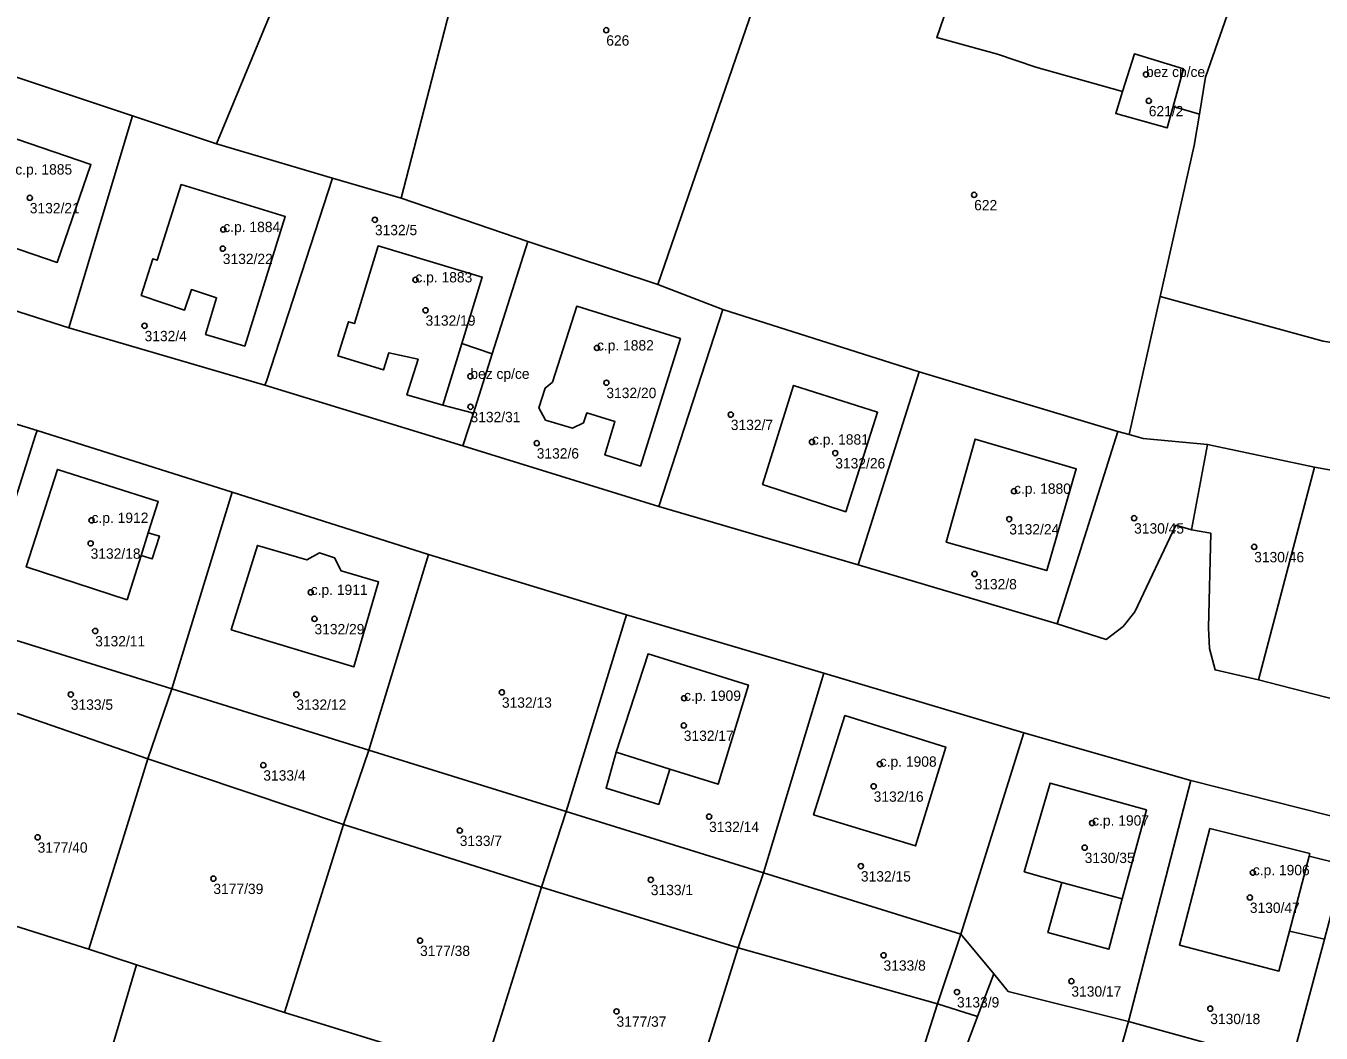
# Model space of a CAD drawing. Extents: x -878211 to -870363, y -1058464 to -1052522.
# Drawn here: x -874523.6 to -874398.3, y -1056692 to -1056594.5 of the extents above; entities that cross this region are included whole.
import ezdxf

# ---------------------------------------------------------------- set-up
doc = ezdxf.new("R2010")
doc.units = 0
for name, color, linetype in [('Definiční body', 7, 'Continuous'), ('Polygon budovy', 7, 'Continuous'), ('Polygon parcely', 7, 'Continuous')]:
    doc.layers.add(name, color=color, linetype=linetype)

msp = doc.modelspace()

# ---------------------------------------------------------------- linework, layer by layer
at = {"layer": 'Definiční body'}
for centre in [(-874467.44, -1056594.87994), (-874415.21, -1056599.15994), (-874414.94, -1056601.71994), (-874523.23, -1056611.10994), (-874431.84, -1056610.81994), (-874504.5, -1056614.16994), (-874489.83, -1056613.22994), (-874504.55, -1056616.01994), (-874485.91, -1056619.03994), (-874484.93, -1056621.98994), (-874512.12, -1056623.48994), (-874468.34, -1056625.62994), (-874480.59, -1056628.37994), (-874467.43, -1056628.99994), (-874480.58, -1056631.32994), (-874455.39, -1056632.08994), (-874474.17, -1056634.84994), (-874447.53, -1056634.73994), (-874445.28, -1056635.80994), (-874427.98, -1056639.49994), (-874517.25, -1056642.31994), (-874428.44, -1056642.19994), (-874416.36, -1056642.10994), (-874517.34, -1056644.54994), (-874404.74, -1056644.88994), (-874431.8, -1056647.50994), (-874496.04, -1056649.28994), (-874495.68, -1056651.85994), (-874516.9, -1056653.02994), (-874519.26, -1056659.16994), (-874497.43, -1056659.16994), (-874477.54, -1056658.96994), (-874459.91, -1056659.53994), (-874459.94, -1056662.17994), (-874500.63, -1056666.01994), (-874440.97, -1056665.91994), (-874441.56, -1056668.06994), (-874457.49, -1056670.99994), (-874420.42, -1056671.61994), (-874522.47, -1056672.99994), (-874481.62, -1056672.34994), (-874421.14, -1056673.99994), (-874505.46, -1056676.99994), (-874442.8, -1056675.78994), (-874404.87, -1056676.41994), (-874463.13, -1056677.10994), (-874405.16, -1056678.82994), (-874485.46, -1056682.99994), (-874440.61, -1056684.41994), (-874422.43, -1056686.92994), (-874433.5, -1056687.97994), (-874466.45, -1056689.84994), (-874408.99, -1056689.58994)]:
    msp.add_circle(centre, 0.25, dxfattribs=at)
at = {"layer": 'Polygon budovy'}
for points in [[(-874417.47, -1056600.82), (-874418.14, -1056602.93), (-874413.16, -1056604.33), (-874412.58, -1056602.26), (-874411.58, -1056598.63), (-874416.33, -1056597.18)], [(-874530.12, -1056614.09), (-874520.57, -1056617.36), (-874517.32, -1056607.88), (-874526.88, -1056604.61)], [(-874508.25, -1056621.96), (-874507.58, -1056619.98), (-874505.15, -1056620.78), (-874506.21, -1056624.33), (-874502.43, -1056625.46), (-874498.5, -1056612.91), (-874508.59, -1056609.82), (-874510.89, -1056617.14), (-874511.33, -1056617), (-874512.45, -1056620.54)], [(-874493.41, -1056626.4), (-874489, -1056627.76), (-874488.48, -1056626.09), (-874485.66, -1056626.72), (-874486.73, -1056630.16), (-874483.25, -1056631.18), (-874481.42, -1056625.19), (-874479.46, -1056618.78), (-874489.51, -1056615.75), (-874491.82, -1056623.27), (-874492.38, -1056623.09)], [(-874473.36, -1056629.52), (-874473.96, -1056631.43), (-874473.32, -1056632.62), (-874470.71, -1056633.4), (-874469.63, -1056632.87), (-874469.33, -1056631.92), (-874466.6, -1056632.74), (-874467.58, -1056635.97), (-874464.13, -1056637.06), (-874460.26, -1056624.73), (-874470.3, -1056621.59), (-874472.65, -1056628.94)], [(-874480.3, -1056631.93), (-874478.49, -1056626.21), (-874481.42, -1056625.19), (-874483.25, -1056631.18)], [(-874452.32, -1056638.84), (-874444.26, -1056641.48), (-874441.18, -1056631.86), (-874449.31, -1056629.26)], [(-874434.54, -1056644.43), (-874424.82, -1056647.18), (-874421.96, -1056637.32), (-874431.73, -1056634.46)], [(-874512.46, -1056645.71), (-874511.76, -1056643.53), (-874510.8, -1056640.5), (-874520.55, -1056637.39), (-874523.57, -1056646.83), (-874513.82, -1056650)], [(-874503.74, -1056652.91), (-874491.88, -1056656.51), (-874489.47, -1056648.28), (-874493.08, -1056647.22), (-874493.73, -1056645.94), (-874495.18, -1056645.48), (-874496.42, -1056646.15), (-874501.2, -1056644.75)], [(-874466.47, -1056664.75), (-874461.3, -1056666.41), (-874456.6, -1056667.86), (-874453.68, -1056658.26), (-874463.4, -1056655.24)], [(-874447.38, -1056670.81), (-874437.51, -1056673.84), (-874434.59, -1056664.26), (-874444.34, -1056661.21)], [(-874426.99, -1056676.34), (-874423.34, -1056677.37), (-874417.51, -1056678.97), (-874415.17, -1056670.35), (-874424.49, -1056667.76)], [(-874399.37, -1056674.57), (-874409.02, -1056672.15), (-874411.97, -1056683.44), (-874402.34, -1056685.95), (-874401.33, -1056682.07), (-874399.42, -1056674.81)]]:
    msp.add_lwpolyline(points, close=True, dxfattribs=at)
at = {"layer": 'Polygon parcely'}
for points in [[(-874482.68, -1056552), (-874492.23, -1056574.63), (-874505.17, -1056605.89), (-874493.95, -1056609.2), (-874487.28, -1056611.12), (-874472.96, -1056555.68), (-874476.32, -1056554.41), (-874477.4, -1056553.99)], [(-874472.96, -1056555.68), (-874487.28, -1056611.12), (-874475.03, -1056615.34), (-874462.44, -1056619.5), (-874452.28, -1056589.96), (-874459.59, -1056587.43), (-874457.06, -1056577.35), (-874452.98, -1056562.31), (-874459.26, -1056559.96), (-874463.6, -1056558.33), (-874472.65, -1056554.94)], [(-874492.23, -1056574.63), (-874501.67, -1056571.24), (-874510.67, -1056567.24), (-874515.54, -1056565.34), (-874527.34, -1056598.5), (-874513.29, -1056603.18), (-874505.17, -1056605.89)], [(-874399.15, -1056580.65), (-874413.96, -1056575.21), (-874417.44, -1056579.26), (-874424.45, -1056585.79), (-874431.52, -1056583.55), (-874433.84, -1056591.24), (-874434.41, -1056592.58), (-874435.46, -1056595.57), (-874429.59, -1056597.21), (-874425.86, -1056598.45), (-874417.47, -1056600.82), (-874416.33, -1056597.18), (-874411.58, -1056598.63), (-874412.58, -1056602.26), (-874410.04, -1056603), (-874409.44, -1056599.43), (-874406.65, -1056591.37)], [(-874425.86, -1056598.45), (-874429.59, -1056597.21), (-874435.46, -1056595.57), (-874434.41, -1056592.58), (-874433.84, -1056591.24), (-874431.52, -1056583.55), (-874448.75, -1056579.37), (-874457.06, -1056577.35), (-874459.59, -1056587.43), (-874452.28, -1056589.96), (-874462.44, -1056619.5), (-874456.17, -1056621.91), (-874437.15, -1056627.95), (-874417.92, -1056633.73), (-874416.85, -1056634), (-874413.84, -1056620.64), (-874410.55, -1056606.05), (-874410.04, -1056603), (-874412.58, -1056602.26), (-874413.16, -1056604.33), (-874418.14, -1056602.93), (-874417.47, -1056600.82)], [(-874390.92, -1056582.93), (-874399.15, -1056580.65), (-874406.65, -1056591.37), (-874409.44, -1056599.43), (-874410.04, -1056603), (-874410.55, -1056606.05), (-874413.84, -1056620.64), (-874398.08, -1056624.97), (-874371.71, -1056629.09), (-874371.71, -1056611.62), (-874372.19, -1056611.57), (-874375.58, -1056611.24), (-874381.94, -1056609.81), (-874392.72, -1056607.44), (-874392.18, -1056604.62), (-874390.79, -1056601.51)], [(-874519.44, -1056623.7), (-874513.29, -1056603.18), (-874527.34, -1056598.5), (-874531.91, -1056597.08), (-874538.75, -1056617.53)], [(-874413.16, -1056604.33), (-874412.58, -1056602.26), (-874411.58, -1056598.63), (-874416.33, -1056597.18), (-874417.47, -1056600.82), (-874418.14, -1056602.93)], [(-874500.32, -1056628.85), (-874493.95, -1056609.2), (-874505.17, -1056605.89), (-874513.29, -1056603.18), (-874519.44, -1056623.7), (-874500.47, -1056629.25)], [(-874526.88, -1056604.61), (-874530.12, -1056614.09), (-874520.57, -1056617.36), (-874517.32, -1056607.88)], [(-874526.88, -1056604.61), (-874517.32, -1056607.88), (-874520.57, -1056617.36), (-874530.12, -1056614.09)], [(-874510.89, -1056617.14), (-874511.33, -1056617), (-874512.45, -1056620.54), (-874508.25, -1056621.96), (-874507.58, -1056619.98), (-874505.15, -1056620.78), (-874506.21, -1056624.33), (-874502.43, -1056625.46), (-874498.5, -1056612.91), (-874508.59, -1056609.82)], [(-874510.89, -1056617.14), (-874508.59, -1056609.82), (-874498.5, -1056612.91), (-874502.43, -1056625.46), (-874506.21, -1056624.33), (-874505.15, -1056620.78), (-874507.58, -1056619.98), (-874508.25, -1056621.96), (-874512.45, -1056620.54), (-874511.33, -1056617)], [(-874489.51, -1056615.75), (-874479.46, -1056618.78), (-874481.42, -1056625.19), (-874478.49, -1056626.21), (-874475.03, -1056615.34), (-874487.28, -1056611.12), (-874493.95, -1056609.2), (-874500.32, -1056628.85), (-874500.47, -1056629.25), (-874481.31, -1056635.12), (-874480.3, -1056631.93), (-874483.25, -1056631.18), (-874486.73, -1056630.16), (-874485.66, -1056626.72), (-874488.48, -1056626.09), (-874489, -1056627.76), (-874493.41, -1056626.4), (-874492.38, -1056623.09), (-874491.82, -1056623.27)], [(-874456.17, -1056621.91), (-874462.44, -1056619.5), (-874475.03, -1056615.34), (-874478.49, -1056626.21), (-874480.3, -1056631.93), (-874481.31, -1056635.12), (-874462.35, -1056640.98)], [(-874483.25, -1056631.18), (-874481.42, -1056625.19), (-874479.46, -1056618.78), (-874489.51, -1056615.75), (-874491.82, -1056623.27), (-874492.38, -1056623.09), (-874493.41, -1056626.4), (-874489, -1056627.76), (-874488.48, -1056626.09), (-874485.66, -1056626.72), (-874486.73, -1056630.16)], [(-874464.13, -1056637.06), (-874467.58, -1056635.97), (-874466.6, -1056632.74), (-874469.33, -1056631.92), (-874469.63, -1056632.87), (-874470.71, -1056633.4), (-874473.32, -1056632.62), (-874473.96, -1056631.43), (-874473.36, -1056629.52), (-874472.65, -1056628.94), (-874470.3, -1056621.59), (-874460.26, -1056624.73)], [(-874464.13, -1056637.06), (-874460.26, -1056624.73), (-874470.3, -1056621.59), (-874472.65, -1056628.94), (-874473.36, -1056629.52), (-874473.96, -1056631.43), (-874473.32, -1056632.62), (-874470.71, -1056633.4), (-874469.63, -1056632.87), (-874469.33, -1056631.92), (-874466.6, -1056632.74), (-874467.58, -1056635.97)], [(-874415.48, -1056634.41), (-874409.26, -1056634.97), (-874398.9, -1056637.18), (-874380.41, -1056640.49), (-874372.85, -1056641.69), (-874371.71, -1056629.09), (-874398.08, -1056624.97), (-874413.84, -1056620.64), (-874416.85, -1056634)], [(-874437.15, -1056627.95), (-874456.17, -1056621.91), (-874462.35, -1056640.98), (-874443.06, -1056646.64)], [(-874478.49, -1056626.21), (-874481.42, -1056625.19), (-874483.25, -1056631.18), (-874480.3, -1056631.93)], [(-874547.67, -1056646.74), (-874528.58, -1056652.68), (-874522.69, -1056634.07), (-874522.52, -1056633.61), (-874542.01, -1056627.68)], [(-874417.92, -1056633.73), (-874437.15, -1056627.95), (-874443.06, -1056646.64), (-874423.82, -1056652.34)], [(-874449.31, -1056629.26), (-874441.18, -1056631.86), (-874444.26, -1056641.48), (-874452.32, -1056638.84)], [(-874449.31, -1056629.26), (-874452.32, -1056638.84), (-874444.26, -1056641.48), (-874441.18, -1056631.86)], [(-874509.49, -1056658.62), (-874503.66, -1056639.59), (-874522.52, -1056633.61), (-874522.69, -1056634.07), (-874528.58, -1056652.68)], [(-874410.8, -1056643.23), (-874409.26, -1056634.97), (-874415.48, -1056634.41), (-874416.85, -1056634), (-874417.92, -1056633.73), (-874423.82, -1056652.34), (-874419.07, -1056653.84), (-874417.43, -1056652.61), (-874416.29, -1056651.16), (-874412.32, -1056642.79)], [(-874421.96, -1056637.32), (-874424.82, -1056647.18), (-874434.54, -1056644.43), (-874431.73, -1056634.46)], [(-874421.96, -1056637.32), (-874431.73, -1056634.46), (-874434.54, -1056644.43), (-874424.82, -1056647.18)], [(-874410.8, -1056643.23), (-874408.93, -1056643.57), (-874409.16, -1056652.73), (-874409.07, -1056654.73), (-874408.53, -1056656.8), (-874404.31, -1056657.76), (-874398.9, -1056637.18), (-874409.26, -1056634.97)], [(-874523.57, -1056646.83), (-874520.55, -1056637.39), (-874510.8, -1056640.5), (-874511.76, -1056643.53), (-874510.69, -1056643.85), (-874511.38, -1056646.05), (-874512.46, -1056645.71), (-874513.82, -1056650)], [(-874523.57, -1056646.83), (-874513.82, -1056650), (-874512.46, -1056645.71), (-874511.38, -1056646.05), (-874510.69, -1056643.85), (-874511.76, -1056643.53), (-874510.8, -1056640.5), (-874520.55, -1056637.39)], [(-874380.41, -1056640.49), (-874398.9, -1056637.18), (-874404.31, -1056657.76), (-874385.91, -1056662.51)], [(-874490.41, -1056664.56), (-874484.66, -1056645.64), (-874503.66, -1056639.59), (-874509.49, -1056658.62)], [(-874493.73, -1056645.94), (-874493.08, -1056647.22), (-874489.47, -1056648.28), (-874491.88, -1056656.51), (-874503.74, -1056652.91), (-874501.2, -1056644.75), (-874496.42, -1056646.15), (-874495.18, -1056645.48)], [(-874493.73, -1056645.94), (-874495.18, -1056645.48), (-874496.42, -1056646.15), (-874501.2, -1056644.75), (-874503.74, -1056652.91), (-874491.88, -1056656.51), (-874489.47, -1056648.28), (-874493.08, -1056647.22)], [(-874465.47, -1056651.46), (-874484.66, -1056645.64), (-874490.41, -1056664.56), (-874471.32, -1056670.5)], [(-874446.38, -1056657.11), (-874465.47, -1056651.46), (-874471.32, -1056670.5), (-874452.23, -1056676.43)], [(-874528.58, -1056652.68), (-874530.51, -1056658.93), (-874511.82, -1056665.4), (-874509.49, -1056658.62)], [(-874453.68, -1056658.26), (-874463.4, -1056655.24), (-874466.47, -1056664.75), (-874467.46, -1056668.23), (-874462.36, -1056669.82), (-874461.3, -1056666.41), (-874456.6, -1056667.86)], [(-874453.68, -1056658.26), (-874456.6, -1056667.86), (-874461.3, -1056666.41), (-874462.36, -1056669.82), (-874467.46, -1056668.23), (-874466.47, -1056664.75), (-874463.4, -1056655.24)], [(-874427.04, -1056662.88), (-874446.38, -1056657.11), (-874452.23, -1056676.43), (-874433.14, -1056682.38)], [(-874536.59, -1056677.84), (-874517.53, -1056683.84), (-874511.82, -1056665.4), (-874530.51, -1056658.93)], [(-874509.49, -1056658.62), (-874511.82, -1056665.4), (-874492.86, -1056671.77), (-874490.41, -1056664.56)], [(-874437.51, -1056673.84), (-874434.59, -1056664.26), (-874444.34, -1056661.21), (-874447.38, -1056670.81)], [(-874437.51, -1056673.84), (-874447.38, -1056670.81), (-874444.34, -1056661.21), (-874434.59, -1056664.26)], [(-874427.04, -1056662.88), (-874433.14, -1056682.38), (-874429.95, -1056686.22), (-874428.55, -1056687.91), (-874416.89, -1056690.83), (-874410.86, -1056667.5)], [(-874512.89, -1056685.34), (-874498.58, -1056689.97), (-874492.86, -1056671.77), (-874511.82, -1056665.4), (-874517.53, -1056683.84)], [(-874473.72, -1056677.82), (-874471.32, -1056670.5), (-874490.41, -1056664.56), (-874492.86, -1056671.77)], [(-874417.51, -1056678.97), (-874418.8, -1056683.83), (-874424.7, -1056682.21), (-874423.34, -1056677.37), (-874426.99, -1056676.34), (-874424.49, -1056667.76), (-874415.17, -1056670.35)], [(-874417.51, -1056678.97), (-874415.17, -1056670.35), (-874424.49, -1056667.76), (-874426.99, -1056676.34), (-874423.34, -1056677.37), (-874424.7, -1056682.21), (-874418.8, -1056683.83)], [(-874409.02, -1056672.15), (-874399.37, -1056674.57), (-874399.42, -1056674.81), (-874396.04, -1056675.67), (-874394.94, -1056671.52), (-874410.86, -1056667.5), (-874416.89, -1056690.83), (-874401.22, -1056695.15), (-874397.95, -1056682.85), (-874401.33, -1056682.07), (-874402.34, -1056685.95), (-874411.97, -1056683.44)], [(-874471.32, -1056670.5), (-874473.72, -1056677.82), (-874454.69, -1056683.71), (-874452.23, -1056676.43)], [(-874396.04, -1056675.67), (-874397.95, -1056682.85), (-874401.22, -1056695.15), (-874385.04, -1056699.32), (-874378.88, -1056675.53), (-874394.94, -1056671.52)], [(-874479.36, -1056695.89), (-874473.72, -1056677.82), (-874492.86, -1056671.77), (-874498.58, -1056689.97)], [(-874396.04, -1056675.67), (-874399.42, -1056674.81), (-874399.37, -1056674.57), (-874409.02, -1056672.15), (-874411.97, -1056683.44), (-874402.34, -1056685.95), (-874401.33, -1056682.07), (-874397.95, -1056682.85)], [(-874520.36, -1056710.57), (-874519.51, -1056707.69), (-874514.47, -1056705.1), (-874517.18, -1056699.85), (-874512.89, -1056685.34), (-874517.53, -1056683.84), (-874536.59, -1056677.84), (-874541.03, -1056676.46), (-874548.64, -1056702.2)], [(-874433.14, -1056682.38), (-874452.23, -1056676.43), (-874454.69, -1056683.71), (-874435.39, -1056689.11)], [(-874473.72, -1056677.82), (-874479.36, -1056695.89), (-874460.36, -1056701.86), (-874454.69, -1056683.71)], [(-874435.39, -1056689.11), (-874431.5, -1056690.35), (-874429.95, -1056686.22), (-874433.14, -1056682.38)], [(-874454.69, -1056683.71), (-874460.36, -1056701.86), (-874441.33, -1056707.79), (-874438.87, -1056700.06), (-874435.39, -1056689.11)], [(-874512.89, -1056685.34), (-874517.18, -1056699.85), (-874514.47, -1056705.1), (-874511.88, -1056710.13), (-874494.62, -1056715.24), (-874486.23, -1056717.71), (-874482.63, -1056706.27), (-874479.36, -1056695.89), (-874498.58, -1056689.97)], [(-874429.95, -1056686.22), (-874431.5, -1056690.35), (-874435.46, -1056700.9), (-874420.78, -1056704.5), (-874416.89, -1056690.83), (-874428.55, -1056687.91)], [(-874438.87, -1056700.06), (-874441.33, -1056707.79), (-874438.03, -1056708.82), (-874435.46, -1056700.9), (-874431.5, -1056690.35), (-874435.39, -1056689.11)], [(-874404.63, -1056708.63), (-874401.71, -1056697.09), (-874401.22, -1056695.15), (-874416.89, -1056690.83), (-874420.78, -1056704.5)]]:
    msp.add_lwpolyline(points, close=True, dxfattribs=at)
for points in [[(-874674.5, -1056611.53), (-874654.24, -1056611.37), (-874630.82, -1056611.95), (-874607.22, -1056614.22), (-874583.78, -1056617.4), (-874585.46, -1056627.16), (-874580.67, -1056628.5), (-874576.97, -1056624.18), (-874577.84, -1056628.61), (-874576.13, -1056629.76), (-874573.21, -1056619.53), (-874560.17, -1056622.07), (-874542.01, -1056627.68), (-874522.52, -1056633.61), (-874503.66, -1056639.59), (-874484.66, -1056645.64), (-874465.47, -1056651.46), (-874446.38, -1056657.11), (-874427.04, -1056662.88), (-874410.86, -1056667.5), (-874394.94, -1056671.52)], [(-874385.91, -1056662.51), (-874404.31, -1056657.76), (-874408.53, -1056656.8), (-874409.07, -1056654.73), (-874409.16, -1056652.73), (-874408.93, -1056643.57), (-874410.8, -1056643.23), (-874412.32, -1056642.79), (-874416.29, -1056651.16), (-874417.43, -1056652.61), (-874419.07, -1056653.84), (-874423.82, -1056652.34), (-874443.06, -1056646.64), (-874462.35, -1056640.98), (-874481.31, -1056635.12), (-874500.47, -1056629.25), (-874519.44, -1056623.7), (-874538.75, -1056617.53)]]:
    msp.add_lwpolyline(points, dxfattribs=at)

# ---------------------------------------------------------------- texts
at = {"layer": 'Definiční body'}
for s, p in [('626', (-874467.44, -1056596.369)), ('bez cp/ce', (-874415.21, -1056599.409)), ('621/2', (-874414.94, -1056603.209)), ('c.p. 1885', (-874524.63, -1056608.85)), ('3132/21', (-874523.23, -1056612.599)), ('622', (-874431.84, -1056612.309)), ('c.p. 1884', (-874504.5, -1056614.419)), ('3132/5', (-874489.83, -1056614.719)), ('3132/22', (-874504.55, -1056617.509)), ('c.p. 1883', (-874485.91, -1056619.29)), ('3132/19', (-874484.93, -1056623.479)), ('3132/4', (-874512.12, -1056624.979)), ('c.p. 1882', (-874468.34, -1056625.879)), ('bez cp/ce', (-874480.59, -1056628.629)), ('3132/20', (-874467.43, -1056630.489)), ('3132/31', (-874480.58, -1056632.819)), ('3132/7', (-874455.39, -1056633.579)), ('c.p. 1881', (-874447.53, -1056634.99)), ('3132/6', (-874474.17, -1056636.339)), ('3132/26', (-874445.28, -1056637.299)), ('c.p. 1880', (-874427.98, -1056639.75)), ('c.p. 1912', (-874517.25, -1056642.57)), ('3132/24', (-874428.44, -1056643.689)), ('3130/45', (-874416.36, -1056643.599)), ('3132/18', (-874517.34, -1056646.039)), ('3130/46', (-874404.74, -1056646.379)), ('c.p. 1911', (-874496.04, -1056649.54)), ('3132/8', (-874431.8, -1056648.999)), ('3132/29', (-874495.68, -1056653.349)), ('3132/11', (-874516.9, -1056654.519)), ('c.p. 1909', (-874459.91, -1056659.79)), ('3133/5', (-874519.26, -1056660.659)), ('3132/12', (-874497.43, -1056660.659)), ('3132/13', (-874477.54, -1056660.459)), ('3132/17', (-874459.94, -1056663.669)), ('c.p. 1908', (-874440.97, -1056666.169)), ('3133/4', (-874500.63, -1056667.509)), ('3132/16', (-874441.56, -1056669.559)), ('3132/14', (-874457.49, -1056672.489)), ('c.p. 1907', (-874420.42, -1056671.87)), ('3133/7', (-874481.62, -1056673.839)), ('3177/40', (-874522.47, -1056674.489)), ('3130/35', (-874421.14, -1056675.489)), ('3132/15', (-874442.8, -1056677.279)), ('c.p. 1906', (-874404.87, -1056676.669)), ('3177/39', (-874505.46, -1056678.489)), ('3133/1', (-874463.13, -1056678.599)), ('3130/47', (-874405.16, -1056680.319)), ('3177/38', (-874485.46, -1056684.489)), ('3133/8', (-874440.61, -1056685.909)), ('3130/17', (-874422.43, -1056688.419)), ('3133/9', (-874433.5, -1056689.469)), ('3177/37', (-874466.45, -1056691.339)), ('3130/18', (-874408.99, -1056691.079))]:
    msp.add_text(s, height=0.999996, dxfattribs=at).set_placement(p)

doc.saveas('drawing.dxf')
